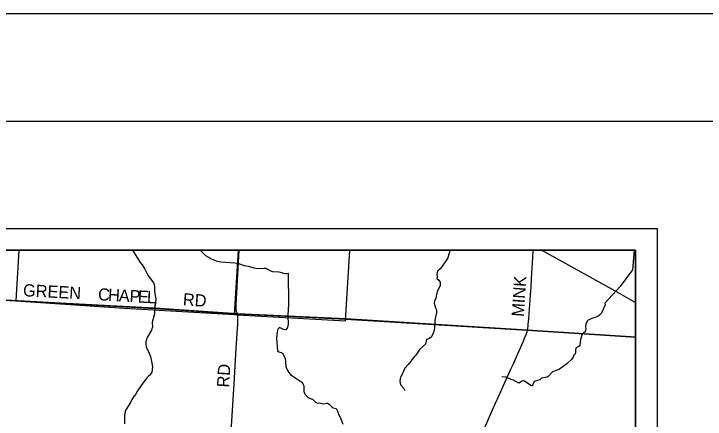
# Model space of a CAD drawing. Extents: x 0 to 91.3, y -0.7 to 22.
# Drawn here: x 6.008 to 9.224, y 20.113 to 22 of the extents above; entities that cross this region are included whole.
import ezdxf

# ---------------------------------------------------------------- set-up
doc = ezdxf.new("R2010")
doc.units = 0
for name, color, linetype in [('GM_X_Corporation', 7, 'Continuous'), ('GM_X_County_Road', 7, 'Continuous'), ('GM_X_County_Road_Text', 7, 'Continuous'), ('GM_X_Minor_River', 7, 'Continuous'), ('GM_X_Township_Road', 7, 'Continuous'), ('GM_X_Township_Road_Text', 7, 'Continuous'), ('SH_Border', 7, 'Continuous'), ('SH_Cut_Line', 7, 'Continuous'), ('SH_Data', 7, 'Continuous')]:
    doc.layers.add(name, color=color, linetype=linetype)

msp = doc.modelspace()

# ---------------------------------------------------------------- linework, layer by layer
at = {"layer": 'GM_X_Corporation'}
for points in [[(8.9, 14.1), (8.9, 20.9), (4.9555, 20.9), (4.9448, 20.7239), (4.9376, 20.6305), (4.9205, 20.3667), (4.8352, 18.7619), (4.834, 18.7568), (4.8336, 18.7529), (4.8277, 18.656), (4.8271, 18.6491), (4.8263, 18.646), (4.8251, 18.6439), (4.8242, 18.6326), (4.7833, 18.1361)], [(8.9, 15.2596), (8.9, 20.4953), (8.8785, 20.4965), (8.3956, 20.5276), (7.5521, 20.5793), (7.0477, 20.6033), (6.6637, 20.6293), (6.253, 20.6521), (5.6061, 20.6867), (4.9448, 20.7239), (4.9376, 20.6305), (4.9205, 20.3667), (4.8352, 18.7619), (4.834, 18.7568), (4.8336, 18.7529), (4.8277, 18.656), (4.8271, 18.6491), (4.8263, 18.646), (4.8251, 18.6439), (4.8242, 18.6326), (4.7833, 18.1361)]]:
    msp.add_lwpolyline(points, dxfattribs=at)
for points in [[(8.9, 20.4953), (8.9, 20.9), (4.9555, 20.9), (4.9448, 20.7239), (5.6061, 20.6867), (6.253, 20.6521), (6.6637, 20.6293), (7.0477, 20.6033), (7.5521, 20.5793), (8.3956, 20.5276), (8.8785, 20.4965)], [(7.053, 20.9), (6.0305, 20.9), (6.0176, 20.6636), (6.5217, 20.6296), (7.0343, 20.5996)], [(7.5706, 20.9), (7.053, 20.9), (7.0343, 20.5996), (7.0467, 20.5989), (7.5501, 20.5711)]]:
    msp.add_lwpolyline(points, close=True, dxfattribs=at)
at = {"layer": 'GM_X_County_Road'}
for points in [[(7.0479, 20.6028), (7.0452, 20.6105), (7.0436, 20.618), (7.0426, 20.6242), (7.0424, 20.6317), (7.0421, 20.6452), (7.0564, 20.9)], [(8.423, 20.9), (8.4208, 20.866), (8.4145, 20.766), (8.4123, 20.7282), (8.4096, 20.6939), (8.4077, 20.6681), (8.4032, 20.6034), (8.4015, 20.5784), (8.3997, 20.5549), (8.3991, 20.5478), (8.3974, 20.535), (8.3958, 20.527)], [(8.4615, 20.9), (8.4713, 20.8945), (8.8024, 20.7116), (8.9, 20.6564)], [(6.93, 18.6467), (6.9336, 18.6494), (6.9353, 18.653), (6.936, 18.6574), (6.9365, 18.6665), (6.9388, 18.7016), (6.9771, 19.3495), (6.9908, 19.5807), (6.9947, 19.6438), (7.001, 19.743), (7.0134, 19.9559), (7.0324, 20.2772), (7.0426, 20.4438), (7.0492, 20.5571), (7.0503, 20.5744), (7.0503, 20.5854), (7.0499, 20.5936), (7.0491, 20.5984), (7.0479, 20.6028)], [(8.3958, 20.527), (8.3937, 20.5185), (8.3894, 20.5053), (8.3839, 20.4912), (8.376, 20.4719), (8.3389, 20.3878), (8.3287, 20.3655), (8.3175, 20.341), (8.2906, 20.2822), (8.2649, 20.2257), (8.2461, 20.1835), (8.2333, 20.1542), (8.198, 20.0731)]]:
    msp.add_lwpolyline(points, dxfattribs=at)
at = {"layer": 'GM_X_Minor_River'}
for points in [[(6.5604, 20.9), (6.5954, 20.8427), (6.6056, 20.831), (6.6177, 20.812), (6.632, 20.7828), (6.6569, 20.7472), (6.6603, 20.7392), (6.6621, 20.7271), (6.6617, 20.7097), (6.6632, 20.6965), (6.6677, 20.673), (6.6654, 20.6412)], [(6.8743, 20.9), (6.8748, 20.8994), (6.9001, 20.8747), (6.9208, 20.8625), (6.9265, 20.8595), (6.9495, 20.85), (6.9707, 20.845), (7.0364, 20.84), (7.0538, 20.8373), (7.0788, 20.8289), (7.0976, 20.8255), (7.1252, 20.8167), (7.1456, 20.8148), (7.1732, 20.8166), (7.18, 20.8158), (7.1887, 20.812), (7.1981, 20.8044), (7.211, 20.7999), (7.2401, 20.7991), (7.268, 20.7918), (7.2744, 20.791), (7.2843, 20.7925), (7.2863, 20.6479)], [(8.0427, 20.9), (8.0425, 20.8997), (8.0368, 20.8944), (8.0308, 20.8812), (8.027, 20.8645), (8.0164, 20.8467), (8.0065, 20.8339), (8.002, 20.8275), (7.9914, 20.8127), (7.9789, 20.8025), (7.9758, 20.787), (7.9777, 20.776), (7.9758, 20.7673), (7.9849, 20.7601), (7.9905, 20.7506), (7.9916, 20.7404), (7.9905, 20.7351), (7.9783, 20.7086), (7.9742, 20.6939), (7.9715, 20.6761), (7.9647, 20.6628), (7.9631, 20.6526)], [(8.8944, 20.9), (8.8862, 20.8082), (8.8279, 20.7311), (8.7579, 20.6525), (8.7594, 20.6457)], [(6.6659, 20.6474), (6.6639, 20.6475), (6.6617, 20.6031), (6.6513, 20.5623), (6.6523, 20.5418), (6.6504, 20.5331), (6.648, 20.5266), (6.6285, 20.4926), (6.622, 20.4722), (6.6212, 20.4654), (6.6237, 20.4494), (6.638, 20.4206), (6.6439, 20.4042), (6.6517, 20.3651), (6.6524, 20.3545), (6.6492, 20.3318), (6.6408, 20.3178), (6.6347, 20.3129), (6.6259, 20.305), (6.6, 20.2691), (6.5801, 20.2397), (6.5717, 20.2238), (6.5659, 20.2178), (6.5575, 20.2042), (6.5502, 20.1902), (6.5284, 20.1562), (6.5254, 20.1467), (6.523, 20.1312), (6.5228, 20.0918)], [(7.2863, 20.6479), (7.2831, 20.5972), (7.2836, 20.5521), (7.2797, 20.5362), (7.2736, 20.5282), (7.2626, 20.531), (7.2433, 20.5402), (7.2357, 20.5315), (7.2326, 20.5198), (7.2302, 20.4906), (7.2344, 20.4314), (7.2412, 20.4264), (7.2476, 20.4256), (7.2533, 20.423), (7.2578, 20.418), (7.262, 20.413), (7.2694, 20.3959), (7.2724, 20.3789), (7.2734, 20.3576), (7.2775, 20.3459), (7.2865, 20.3306), (7.2956, 20.3215), (7.3065, 20.3135), (7.3484, 20.2848), (7.3529, 20.2791), (7.3574, 20.2665), (7.3566, 20.2487), (7.3577, 20.24), (7.3644, 20.2263), (7.3765, 20.2137), (7.3995, 20.2045), (7.4124, 20.1907), (7.4237, 20.1873), (7.4298, 20.1884), (7.4487, 20.1841), (7.4628, 20.1878), (7.4677, 20.1874), (7.4745, 20.1835), (7.4809, 20.1767), (7.4881, 20.1694), (7.4941, 20.166), (7.5066, 20.1625), (7.5141, 20.1496), (7.5219, 20.1279), (7.5265, 20.1226), (7.5377, 20.0903)], [(7.9631, 20.6526), (7.9691, 20.631), (7.9744, 20.6223), (7.9747, 20.6086), (7.9665, 20.5741), (7.9652, 20.5419), (7.964, 20.5253), (7.9593, 20.5128), (7.9505, 20.4961), (7.9418, 20.489), (7.9342, 20.4852), (7.9281, 20.4841), (7.9223, 20.4626), (7.8967, 20.4385), (7.8784, 20.4101), (7.8715, 20.4045), (7.8425, 20.3675), (7.8269, 20.3509), (7.8138, 20.3226), (7.8092, 20.3142), (7.8062, 20.3082), (7.8042, 20.2908), (7.8052, 20.2805), (7.8086, 20.2718), (7.8222, 20.2554), (7.8267, 20.247)], [(8.7594, 20.6457), (8.7412, 20.6063), (8.7328, 20.5968), (8.7245, 20.5901), (8.6967, 20.5815), (8.6796, 20.5737), (8.6747, 20.5699), (8.6681, 20.5552), (8.6666, 20.5445), (8.6684, 20.5354), (8.6657, 20.5192), (8.6512, 20.5086), (8.6439, 20.4836), (8.6414, 20.4579), (8.6384, 20.453), (8.6235, 20.4447), (8.6201, 20.4356), (8.6204, 20.4303), (8.6211, 20.4201), (8.6177, 20.414), (8.6124, 20.4103), (8.6093, 20.4012), (8.6035, 20.3921), (8.581, 20.3699), (8.5468, 20.3455), (8.54, 20.3432), (8.513, 20.3339), (8.4939, 20.312), (8.4882, 20.3083), (8.4631, 20.3035), (8.4548, 20.2967), (8.4286, 20.2882), (8.4217, 20.2746), (8.4205, 20.2685), (8.4156, 20.2685), (8.3808, 20.2911), (8.3721, 20.29), (8.3572, 20.2803), (8.3327, 20.2937), (8.3221, 20.2975), (8.2967, 20.3083), (8.2778, 20.3107)]]:
    msp.add_lwpolyline(points, dxfattribs=at)
at = {"layer": 'GM_X_Township_Road'}
msp.add_lwpolyline([(5.6063, 20.6862), (6.2532, 20.6515), (6.6639, 20.6288), (7.0479, 20.6028), (7.5524, 20.5788), (8.3958, 20.527), (8.8787, 20.4959), (8.9, 20.4948)], dxfattribs=at)
at = {"layer": 'SH_Border'}
msp.add_lwpolyline([(1.5, 21.5), (33.5, 21.5), (33.5, 0.5), (1.5, 0.5)], close=True, dxfattribs=at)
at = {"layer": 'SH_Cut_Line'}
msp.add_lwpolyline([(0, 0), (34, 0), (34, 22), (0, 22)], close=True, dxfattribs=at)
at = {"layer": 'SH_Data'}
for p, q in [((2, 21), (9, 21)), ((9, 21), (9, 14)), ((2.1, 20.9), (8.9, 20.9)), ((8.9, 20.9), (8.9, 14.1))]:
    msp.add_line(p, q, dxfattribs=at)

# ---------------------------------------------------------------- texts
at = {"layer": 'GM_X_County_Road_Text'}
for s, rotation, p in [('MINK', 86.1689, (8.3799, 20.5883)), ('RD', 86.5503, (7.0091, 20.2591))]:
    msp.add_text(s, height=0.05682, rotation=rotation, dxfattribs=at).set_placement(p)
at = {"layer": 'GM_X_Township_Road_Text'}
for s, height, rotation, p in [('GREEN', 0.05682, 356.9099, (6.0494, 20.6857)), ('C', 0.0568, 356.7823, (6.3985, 20.6665)), ('H', 0.0568, 356.7781, (6.4451, 20.6639)), ('A', 0.0568, 356.7817, (6.495, 20.6611)), ('P', 0.0568, 356.7821, (6.5449, 20.6583)), ('E', 0.0568, 356.7902, (6.5832, 20.6561)), ('L', 0.0568, 357.2111, (6.6261, 20.6537)), ('RD', 0.05682, 356.0551, (6.7929, 20.6431))]:
    msp.add_text(s, height=height, rotation=rotation, dxfattribs=at).set_placement(p)

doc.saveas('drawing.dxf')
